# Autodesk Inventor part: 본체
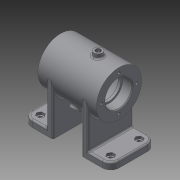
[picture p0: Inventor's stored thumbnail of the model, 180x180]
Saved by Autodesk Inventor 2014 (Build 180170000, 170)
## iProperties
Created: 2017-02
Part Number: 본체
Material: 일반
Document SubType Name: Modeling
Designer: user
Density: 1 g/cm^3
Appearance: 기본값
Author: user
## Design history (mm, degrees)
sketch "스케치1"
  geometry: C1 r 27 at (0, 0); 1 further point
  constraints: 1 centre point, 1 coincident
  dimensions: "d0" = 54 diameter of C1
extrude "돌출1" new body sketch "스케치1" stored distance "d1" = 70; taper "d2" = 0 deg
node "작업 평면1"
sketch "스케치2"
  geometry: L1 (27, 52)-(-27, 52); L2 (-27, 52)-(-27, 17); L3 (-27, 17)-(27, 17); L4 (27, 17)-(27, 52); L5 (27, 52)-(-27, 17); L6 (-27, 52)-(27, 17); 2 further points
  constraints: 12 end point, 2 midpoint, 2 parallel, 1 horizontal, 1 perpendicular
  dimensions: "d5" = 52 distance from line of point (0, 0) L1; "d6" = 17 distance from line of point (0, 0) L3; "d7" = 54 distance between parallel lines of L2 L4
extrude "돌출2" join sketch "스케치2" distance "d8" = 8; taper "d9" = 0 deg
sketch "스케치3"
  geometry: L1 (-8, 0)-(-8, 54) reference; L2 (-60, 0)-(-8, 0); L3 (-60, 54)-(-8, 54); L4 (0, 0)-(0, 54) reference; A1 r 27 centre (-60, 27) between (-60, 0) and (-60, 54) reference; A2 r 27 centre (-60, 27) between (-60, 0) and (-60, 54); 1 further point
  constraints: 4 end point, 4 point on circle, 2 tangent, 1 centre point, 1 coincident, 1 concentric, 1 parallel, 1 perpendicular
  dimensions: "d50" = 60 distance from line of point (-60, 27) L4 (derived); "d51" = 8 distance between parallel lines of L1 L4 (derived)
extrude "돌출3" join sketch "스케치3" distance "d10" = 8; taper "d11" = 0 deg
sketch "스케치4"
  geometry: L1 (0, -35)-(0, 35); L2 (-16, -35)-(-16, -23.3); L3 (-15.7, -23)-(-14, -23); L4 (-14, -23)-(-14, -20); L5 (-14, -20)-(-19, -20); L6 (-22, -17)-(-22, 17); L7 (-19, 20)-(-14, 20); L8 (-14, 20)-(-14, 23); L9 (-14, 23)-(-15.7, 23); L10 (-16, 23.3)-(-16, 35); L11 (27, 35)-(-27, 35) reference; L12 (-27, -35)-(27, -35) reference; L13 (-16, 35)-(0, 35); L14 (-16, -35)-(0, -35); A1 r 3 centre (-19, -17) between (-22, -17) and (-19, -20); A2 r 3 centre (-19, 17) between (-19, 20) and (-22, 17); A3 r 0.3 centre (-15.7, -23.3) between (-15.7, -23) and (-16, -23.3); A4 r 0.3 centre (-15.7, 23.3) between (-16, 23.3) and (-15.7, 23); 2 further points
  constraints: 24 end point, 8 point on circle, 8 tangent, 6 parallel, 4 centre point, 2 equal radius, 2 perpendicular, 2 point on line, 1 coincident, 1 collinear, 1 midpoint, 1 vertical
  dimensions: "d12" = 70 distance of L1.start L1.end; "d13" = 12 distance between parallel lines of L3 L12; "d14" = 12 distance between parallel lines of L9 L11; "d15" = 40 distance between parallel lines of L7 L5; "d17" = 3 distance between parallel lines of L3 L5; "d18" = 3 distance between parallel lines of L9 L7 (derived); "d19" = 32 diameter of L2 L1; "d20" = 32 diameter of L10 L1; "d21" = 28 diameter of L8 L1; "d22" = 28 diameter of L4 L1; "d23" = 44 diameter of L6 L1; "d24" = 3 radius of A1; "d25" = 0.3 radius of A3
revolve "회전1" sketch "스케치4" stored, may be unused: angle "d26" = 90 deg
chamfer "모따기1" distance "d27" = 1; stored, may be unused: second distance "d28" = 2, angle "d29" = 45 deg
sketch "스케치5"
  geometry: L1 (0, 21)-(0, -21); L2 (21, 0)-(-21, 0); C1 r 17 at (0, 0) reference; A1 r 21 centre (0, 0) between (0, 21) and (21, 0)
  constraints: 4 end point, 4 point on circle, 1 centre point, 1 coincident, 1 perpendicular, 1 vertical
  dimensions: "d30" = 42 diameter of A1; "d31" = 42 distance of L2.start L2.end; "d32" = 42 distance of L1.start L1.end
hole "구멍1" sketch "스케치5" at (0, 21), (21, 0), (0, -21), (-21, 0) diameter "d33" = 3.242; stored, may be unused: countersink angle "d37" = 90 deg, drill point angle "d39" = 118 deg; dims "d34" = 8, "d35" = 4, "d36" = 2, "d38" = 10
node "작업 평면2"
node "작업 평면4"
sketch "스케치8"
  geometry: L1 (0, 0)-(-25.16, -16.339); L2 (-60, 27)-(-60, -27) reference; L3 (0, 0)-(-60, 0)
  constraints: 4 end point, 1 midpoint
  dimensions: "d53" = 30 distance of L1.start L1.end; "d54" = 33 deg angle of L1 L3
node "작업 평면3"
sketch "스케치9"
  geometry: C1 r 6 at (0, 0); 1 further point
  constraints: 1 centre point, 1 coincident
  dimensions: "d55" = 12 diameter of C1
extrude "돌출6" join sketch "스케치9" stored distance "d56" = 5; taper "d57" = 0 deg
sketch "스케치10"
  geometry: C1 r 6 at (0, 0) reference; C2 r 3 at (0, 0)
  constraints: 1 centre point, 1 coincident
  dimensions: "d58" = 6 diameter of C2
extrude "돌출7" cut sketch "스케치10" distance "d59" = 20; taper "d60" = 0 deg
feature "스레드2" dims "d61" = 10, "d62" = 0
fillet "모깎기2" dims "d63" = 2
fillet "모깎기3" dims "d64" = 10
fillet "모깎기4" dims "d65" = 10
sketch "스케치11"
  geometry: L1 (45, -27)-(45, 27) reference; C1 r 5 at (20, 0); 1 further point
  constraints: 1 centre point, 1 horizontal alignment
  dimensions: "d66" = 10 diameter of C1; "d67" = 25 distance from line of C1.centre L1
extrude "돌출8" join sketch "스케치11" stored distance "d68" = 20; taper "d69" = 0 deg
sketch "스케치12"
  geometry: C1 r 5 at (0, 0) reference; C2 r 3 at (0, 0); 1 further point
  constraints: 1 centre point, 1 coincident
  dimensions: "d70" = 6 diameter of C2
extrude "돌출9" cut sketch "스케치12" distance "d71" = 15; taper "d72" = 0 deg
fillet "모깎기5" dims "d73" = 2
feature "스레드3" dims "d74" = 10, "d75" = 0
node "작업 평면5"
sketch "스케치13"
  geometry: L1 (-79, -10)-(-79, 60) reference; L2 (-79, -10)-(-25, -10) reference; 2 further points
  constraints: 1 other
  dimensions: "d76" = 27 distance from line of L1 point (-52, 25); "d77" = 35 distance from line of point (-52, 25) L2
feature "엠보싱1" sketch "스케치13" dims "d0" = 54, "d78" = 0.5, "d79" = 0
sketch "스케치14" dims "d80" = 9, "d81" = 9
  geometry: L1 (21.5, 10)-(19.25, 6.103); L2 (19.25, 6.103)-(14.75, 6.103); L3 (14.75, 6.103)-(12.5, 10); L4 (12.5, 10)-(14.75, 13.897); L5 (14.75, 13.897)-(19.25, 13.897); L6 (19.25, 13.897)-(21.5, 10); L7 (21.5, 44)-(19.25, 40.103); L8 (19.25, 40.103)-(14.75, 40.103); L9 (14.75, 40.103)-(12.5, 44); L10 (12.5, 44)-(14.75, 47.897); L11 (14.75, 47.897)-(19.25, 47.897); L12 (19.25, 47.897)-(21.5, 44); A1 r 10 centre (17, 44) between (27, 44) and (17, 54) reference; A2 r 10 centre (17, 10) between (17, 0) and (27, 10) reference; 5 further points
  constraints: 24 end point, 4 coincident, 2 horizontal alignment, 30 other
  dimensions: "d82" = 3.89711 vertical distance of L2.end L3.end; "d83" = 3.89711 vertical distance of L8.end L9.end
extrude "돌출10" cut sketch "스케치14" distance "d84" = 3; taper "d85" = 0 deg
sketch "스케치15"
  geometry: C1 r 2.5 at (-25, 44); C2 r 2.5 at (-25, 10); A1 r 10 centre (-25, 44) between (-25, 54) and (-35, 44) reference; A2 r 10 centre (-25, 10) between (-35, 10) and (-25, 0) reference; 1 further point
  constraints: 2 centre point, 2 coincident
  dimensions: "d86" = 5 diameter of C1; "d87" = 5 diameter of C2
extrude "돌출11" cut sketch "스케치15" distance "d88" = 8; taper "d89" = 0 deg
fillet "모깎기6" dims "d90" = 2
fillet "모깎기7" dims "d91" = 2
fillet "모깎기8" dims "d92" = 2
fillet "모깎기9" dims "d93" = 2
node "솔리드1"
mirror "대칭1"
mirror "대칭2"
mirror "대칭3"
other parameters: "d40" = -92
